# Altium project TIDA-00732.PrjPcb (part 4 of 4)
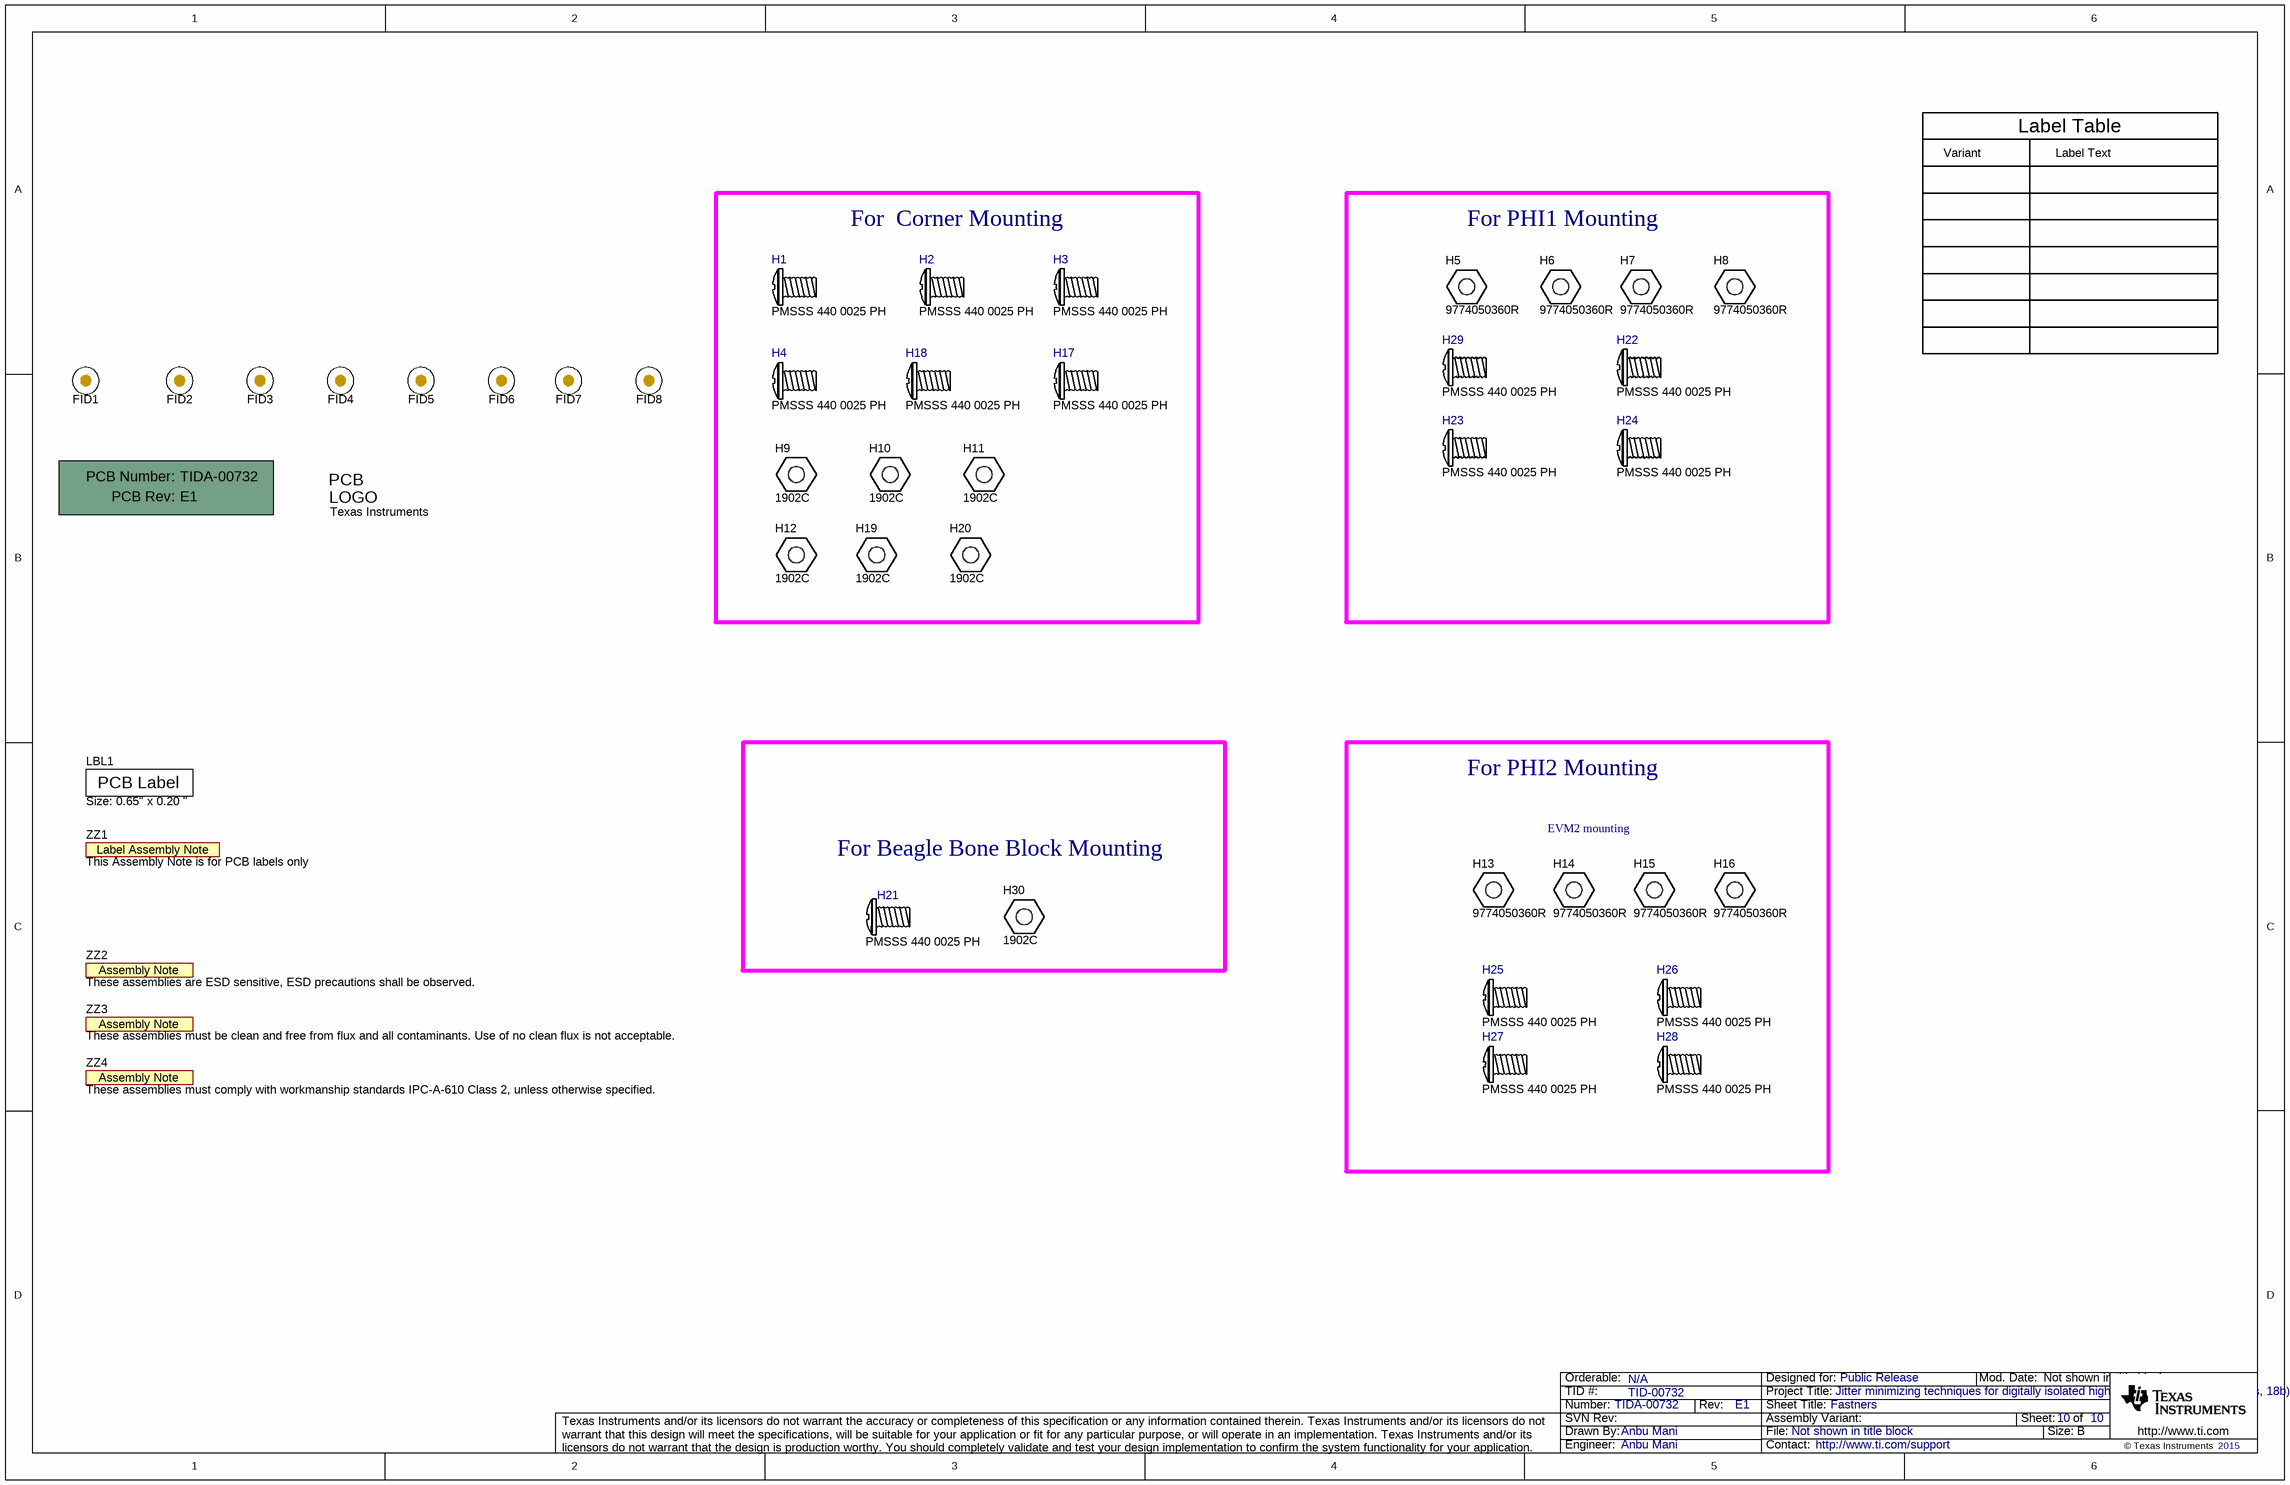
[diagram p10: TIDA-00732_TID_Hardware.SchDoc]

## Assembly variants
ADS9110 w/REF5045: not fitted C69 C72 C214 FID1 FID2 FID3 J24 R45 R48 R53 R54 R56 R57 R59 R60 R64 R65 R66 R68 R69 R77 R78 R79 R81 R82 R100 R102
ADS9110 w/REF6041: not fitted C69 C72 C214 J24 R45 R49 R55 R58 R64 R65 R66 R68 R69 R77 R78 R79 R81 R82 R100 R102
ADS8900(20bitADC) w/REF5045: not fitted C214 FID1 FID2 FID3 J24 R45 R48 R49 R53 R54 R56 R57 R59 R60 R64 R65 R66 R68 R69 R77 R78 R79 R81 R82 R208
